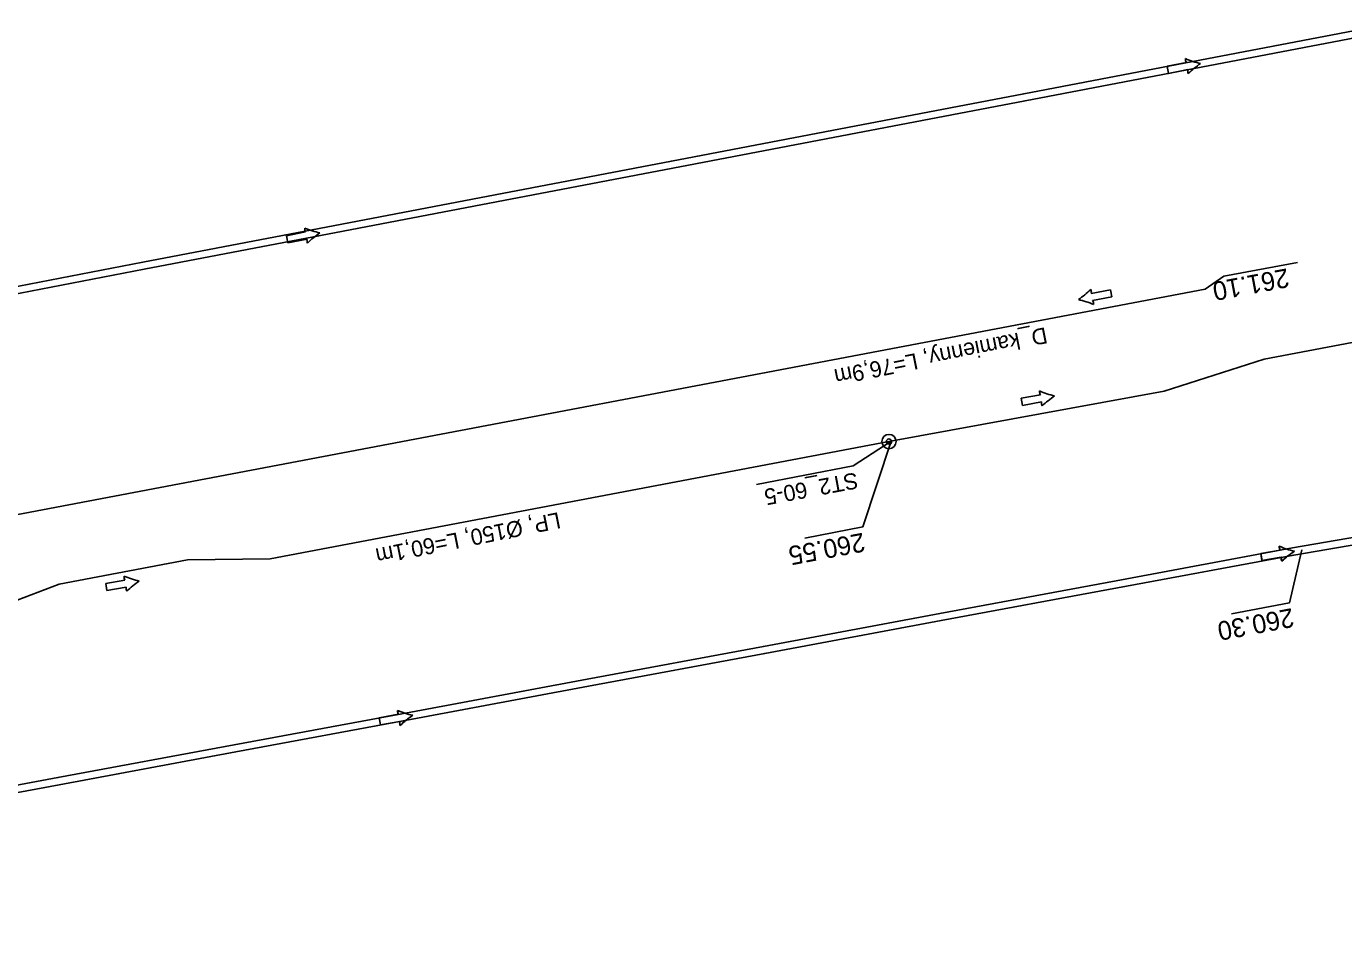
# Model space of a CAD drawing. Extents: x -1 to 65640748, y -22 to 5530284.
# Drawn here: x 6558708.2 to 6558781.6, y 5528891 to 5528942.3 of the extents above; entities that cross this region are included whole.
import ezdxf

# ---------------------------------------------------------------- set-up
doc = ezdxf.new("R2010")
doc.units = 0
for name, color, linetype in [('TOR_PS_ODW-drenaze', 7, 'Continuous'), ('TOR_PS_ODW-drenokolektory', 7, 'Continuous'), ('TOR_PS_ODW-studnie PEHD', 7, 'Continuous'), ('TOR_PS_OPIS_O-opisy rurociagow', 7, 'Continuous'), ('TOR_PS_OPIS_O-opisy studni', 7, 'Continuous'), ('TOR_PS_OPIS_T-INFO', 7, 'Continuous'), ('TOR_PS_T-rowy otwarte umocnione', 7, 'Continuous')]:
    doc.layers.add(name, color=color, linetype=linetype)

msp = doc.modelspace()

# ---------------------------------------------------------------- linework, layer by layer
at = {"layer": 'TOR_PS_ODW-drenaze'}
msp.add_line((6558773.925, 5528927.61), (6558698.366, 5528913.287), dxfattribs=at)
at = {"layer": 'TOR_PS_ODW-drenokolektory'}
for points in [[(6558810.39, 5528929.053), (6558807.044, 5528928.439), (6558801.771, 5528928.372), (6558793.907, 5528926.881), (6558787.408, 5528925.65), (6558777.206, 5528923.716), (6558771.626, 5528921.937), (6558756.292, 5528919.127)], [(6558756.292, 5528919.127), (6558721.8, 5528912.589), (6558717.193, 5528912.53), (6558710.034, 5528911.173), (6558705.725, 5528909.542), (6558705.725, 5528909.542), (6558697.342, 5528907.953)]]:
    msp.add_lwpolyline(points, dxfattribs=at)
at = {"layer": 'TOR_PS_ODW-studnie PEHD'}
for radius in [0.4, 0.145]:
    msp.add_circle((6558756.292, 5528919.127), radius, dxfattribs=at)
at = {"layer": 'TOR_PS_OPIS_O-opisy rurociagow'}
for p, q in [((6558772.874, 5528940.248), (6558771.801, 5528940.041)), ((6558772.874, 5528940.248), (6558771.801, 5528940.041)), ((6558772.874, 5528940.248), (6558771.801, 5528940.041)), ((6558772.874, 5528940.248), (6558771.801, 5528940.041)), ((6558771.801, 5528940.041), (6558771.876, 5528939.648)), ((6558771.801, 5528940.041), (6558771.876, 5528939.648)), ((6558771.801, 5528940.041), (6558771.876, 5528939.648)), ((6558771.801, 5528940.041), (6558771.876, 5528939.648)), ((6558771.876, 5528939.648), (6558772.949, 5528939.855)), ((6558772.949, 5528939.855), (6558771.876, 5528939.648)), ((6558771.876, 5528939.648), (6558772.949, 5528939.855)), ((6558772.949, 5528939.855), (6558771.876, 5528939.648)), ((6558723.773, 5528930.805), (6558722.7, 5528930.599)), ((6558723.773, 5528930.805), (6558722.7, 5528930.599)), ((6558723.773, 5528930.805), (6558722.7, 5528930.599)), ((6558723.773, 5528930.805), (6558722.7, 5528930.599)), ((6558722.7, 5528930.599), (6558722.776, 5528930.206)), ((6558722.7, 5528930.599), (6558722.776, 5528930.206)), ((6558722.7, 5528930.599), (6558722.776, 5528930.206)), ((6558722.7, 5528930.599), (6558722.776, 5528930.206)), ((6558722.776, 5528930.206), (6558723.849, 5528930.413)), ((6558723.849, 5528930.413), (6558722.776, 5528930.206)), ((6558722.776, 5528930.206), (6558723.849, 5528930.413)), ((6558723.849, 5528930.413), (6558722.776, 5528930.206)), ((6558768.647, 5528927.581), (6558767.573, 5528927.378)), ((6558767.573, 5528927.378), (6558768.647, 5528927.581)), ((6558768.721, 5528927.188), (6558768.647, 5528927.581)), ((6558768.721, 5528927.188), (6558768.647, 5528927.581)), ((6558767.648, 5528926.985), (6558768.721, 5528927.188)), ((6558767.648, 5528926.985), (6558768.721, 5528927.188)), ((6558764.734, 5528921.726), (6558763.659, 5528921.535)), ((6558764.734, 5528921.726), (6558763.659, 5528921.535)), ((6558763.659, 5528921.535), (6558763.729, 5528921.141)), ((6558763.659, 5528921.535), (6558763.729, 5528921.141)), ((6558763.729, 5528921.141), (6558764.805, 5528921.332)), ((6558764.805, 5528921.332), (6558763.729, 5528921.141)), ((6558778.099, 5528913.074), (6558777.022, 5528912.892)), ((6558778.099, 5528913.074), (6558777.022, 5528912.892)), ((6558778.099, 5528913.074), (6558777.022, 5528912.892)), ((6558778.099, 5528913.074), (6558777.022, 5528912.892)), ((6558777.022, 5528912.892), (6558777.089, 5528912.497)), ((6558777.022, 5528912.892), (6558777.089, 5528912.497)), ((6558777.022, 5528912.892), (6558777.089, 5528912.497)), ((6558777.022, 5528912.892), (6558777.089, 5528912.497)), ((6558778.107, 5528913.076), (6558777.03, 5528912.893)), ((6558778.107, 5528913.076), (6558777.03, 5528912.893)), ((6558777.03, 5528912.893), (6558777.097, 5528912.499)), ((6558777.03, 5528912.893), (6558777.097, 5528912.499)), ((6558777.089, 5528912.497), (6558778.166, 5528912.68)), ((6558778.166, 5528912.68), (6558777.089, 5528912.497)), ((6558777.089, 5528912.497), (6558778.166, 5528912.68)), ((6558778.166, 5528912.68), (6558777.089, 5528912.497)), ((6558777.097, 5528912.499), (6558778.174, 5528912.681)), ((6558778.174, 5528912.681), (6558777.097, 5528912.499)), ((6558713.7, 5528911.407), (6558712.625, 5528911.215)), ((6558713.7, 5528911.407), (6558712.625, 5528911.215)), ((6558712.625, 5528911.215), (6558712.695, 5528910.821)), ((6558712.625, 5528911.215), (6558712.695, 5528910.821)), ((6558712.695, 5528910.821), (6558713.77, 5528911.013)), ((6558713.77, 5528911.013), (6558712.695, 5528910.821)), ((6558728.944, 5528903.922), (6558727.87, 5528903.722)), ((6558728.944, 5528903.922), (6558727.87, 5528903.722)), ((6558728.944, 5528903.922), (6558727.87, 5528903.722)), ((6558728.944, 5528903.922), (6558727.87, 5528903.722)), ((6558728.946, 5528903.922), (6558727.871, 5528903.722)), ((6558728.946, 5528903.922), (6558727.871, 5528903.722)), ((6558727.87, 5528903.722), (6558727.943, 5528903.329)), ((6558727.87, 5528903.722), (6558727.943, 5528903.329)), ((6558727.87, 5528903.722), (6558727.943, 5528903.329)), ((6558727.87, 5528903.722), (6558727.943, 5528903.329)), ((6558727.871, 5528903.722), (6558727.945, 5528903.329)), ((6558727.871, 5528903.722), (6558727.945, 5528903.329)), ((6558727.943, 5528903.329), (6558729.017, 5528903.528)), ((6558729.017, 5528903.528), (6558727.943, 5528903.329)), ((6558727.943, 5528903.329), (6558729.017, 5528903.528)), ((6558729.017, 5528903.528), (6558727.943, 5528903.329)), ((6558727.945, 5528903.329), (6558729.019, 5528903.529)), ((6558729.019, 5528903.529), (6558727.945, 5528903.329))]:
    msp.add_line(p, q, dxfattribs=at)
for points in [[(6558772.821, 5528940.466), (6558772.821, 5528940.466)], [(6558772.821, 5528940.466), (6558772.821, 5528940.466)], [(6558772.981, 5528939.632), (6558772.981, 5528939.632)], [(6558772.981, 5528939.632), (6558772.981, 5528939.632)], [(6558723.721, 5528931.024), (6558723.721, 5528931.024)], [(6558723.721, 5528931.024), (6558723.721, 5528931.024)], [(6558723.881, 5528930.19), (6558723.881, 5528930.19)], [(6558723.881, 5528930.19), (6558723.881, 5528930.19)], [(6558767.541, 5528927.601), (6558767.541, 5528927.601)], [(6558767.7, 5528926.766), (6558767.7, 5528926.766)], [(6558764.685, 5528921.946), (6558764.685, 5528921.946)], [(6558764.834, 5528921.109), (6558764.834, 5528921.109)], [(6558778.051, 5528913.294), (6558778.051, 5528913.294)], [(6558778.051, 5528913.294), (6558778.051, 5528913.294)], [(6558778.059, 5528913.296), (6558778.059, 5528913.296)], [(6558778.193, 5528912.457), (6558778.193, 5528912.457)], [(6558778.193, 5528912.457), (6558778.193, 5528912.457)], [(6558778.202, 5528912.458), (6558778.202, 5528912.458)], [(6558713.651, 5528911.626), (6558713.651, 5528911.626)], [(6558713.8, 5528910.79), (6558713.8, 5528910.79)], [(6558728.893, 5528904.141), (6558728.893, 5528904.141)], [(6558728.893, 5528904.141), (6558728.893, 5528904.141)], [(6558728.894, 5528904.141), (6558728.894, 5528904.141)], [(6558729.048, 5528903.305), (6558729.048, 5528903.305)], [(6558729.048, 5528903.305), (6558729.048, 5528903.305)], [(6558729.05, 5528903.306), (6558729.05, 5528903.306)]]:
    msp.add_lwpolyline(points, dxfattribs=at)
for centre, radius, start, end in [((6558774.728, 5528944.999), 4.918, 247.17871, 257.56053), ((6558773.279, 5528940.461), 0.458, 179.29327, 207.75451), ((6558774.728, 5528944.999), 4.918, 247.17871, 257.56053), ((6558773.279, 5528940.461), 0.458, 179.29327, 207.75451), ((6558774.728, 5528944.999), 4.918, 247.17871, 257.56053), ((6558773.279, 5528940.461), 0.458, 179.29327, 207.75451), ((6558774.728, 5528944.999), 4.918, 247.17871, 257.56053), ((6558773.279, 5528940.461), 0.458, 179.29327, 207.75451), ((6558773.405, 5528939.807), 0.458, 174.02262, 202.48386), ((6558773.405, 5528939.807), 0.458, 174.02262, 202.48386), ((6558773.405, 5528939.807), 0.458, 174.02262, 202.48386), ((6558773.405, 5528939.807), 0.458, 174.02262, 202.48386), ((6558776.434, 5528936.13), 4.918, 124.21659, 134.59842), ((6558776.434, 5528936.13), 4.918, 124.21659, 134.59842), ((6558776.434, 5528936.13), 4.918, 124.21659, 134.59842), ((6558776.434, 5528936.13), 4.918, 124.21659, 134.59842), ((6558725.628, 5528935.557), 4.918, 247.17871, 257.56053), ((6558724.178, 5528931.019), 0.458, 179.29327, 207.75451), ((6558725.628, 5528935.557), 4.918, 247.17871, 257.56053), ((6558724.178, 5528931.019), 0.458, 179.29327, 207.75451), ((6558725.628, 5528935.557), 4.918, 247.17871, 257.56053), ((6558724.178, 5528931.019), 0.458, 179.29327, 207.75451), ((6558725.628, 5528935.557), 4.918, 247.17871, 257.56053), ((6558724.178, 5528931.019), 0.458, 179.29327, 207.75451), ((6558724.304, 5528930.365), 0.458, 174.02262, 202.48386), ((6558724.304, 5528930.365), 0.458, 174.02262, 202.48386), ((6558724.304, 5528930.365), 0.458, 174.02262, 202.48386), ((6558724.304, 5528930.365), 0.458, 174.02262, 202.48386), ((6558727.334, 5528926.688), 4.918, 124.21659, 134.59842), ((6558727.334, 5528926.688), 4.918, 124.21659, 134.59842), ((6558727.334, 5528926.688), 4.918, 124.21659, 134.59842), ((6558727.334, 5528926.688), 4.918, 124.21659, 134.59842), ((6558764.098, 5528931.112), 4.918, 304.06127, 314.4431), ((6558764.098, 5528931.112), 4.918, 304.06127, 314.4431), ((6558767.118, 5528927.427), 0.458, 353.86729, 22.32853), ((6558767.118, 5528927.427), 0.458, 353.86729, 22.32853), ((6558765.78, 5528922.238), 4.918, 67.02338, 77.40521), ((6558765.78, 5528922.238), 4.918, 67.02338, 77.40521), ((6558767.242, 5528926.773), 0.458, 359.13794, 27.59919), ((6558767.242, 5528926.773), 0.458, 359.13794, 27.59919), ((6558766.655, 5528926.452), 4.918, 246.38098, 256.76281), ((6558765.142, 5528921.934), 0.458, 178.49555, 206.95679), ((6558766.655, 5528926.452), 4.918, 246.38098, 256.76281), ((6558765.142, 5528921.934), 0.458, 178.49555, 206.95679), ((6558768.238, 5528917.56), 4.918, 123.41887, 133.8007), ((6558768.238, 5528917.56), 4.918, 123.41887, 133.8007), ((6558765.259, 5528921.278), 0.458, 173.22489, 201.68613), ((6558765.259, 5528921.278), 0.458, 173.22489, 201.68613), ((6558780.057, 5528917.784), 4.918, 245.92481, 256.30664), ((6558778.509, 5528913.279), 0.458, 178.03937, 206.50061), ((6558780.057, 5528917.784), 4.918, 245.92481, 256.30664), ((6558778.509, 5528913.279), 0.458, 178.03937, 206.50061), ((6558780.057, 5528917.784), 4.918, 245.92481, 256.30664), ((6558778.509, 5528913.279), 0.458, 178.03937, 206.50061), ((6558780.057, 5528917.784), 4.918, 245.92481, 256.30664), ((6558778.509, 5528913.279), 0.458, 178.03937, 206.50061), ((6558780.065, 5528917.786), 4.918, 245.92481, 256.30664), ((6558778.517, 5528913.28), 0.458, 178.03937, 206.50061), ((6558780.065, 5528917.786), 4.918, 245.92481, 256.30664), ((6558778.517, 5528913.28), 0.458, 178.03937, 206.50061), ((6558778.62, 5528912.622), 0.458, 172.76872, 201.22996), ((6558778.62, 5528912.622), 0.458, 172.76872, 201.22996), ((6558778.62, 5528912.622), 0.458, 172.76872, 201.22996), ((6558778.62, 5528912.622), 0.458, 172.76872, 201.22996), ((6558778.628, 5528912.624), 0.458, 172.76872, 201.22996), ((6558778.628, 5528912.624), 0.458, 172.76872, 201.22996), ((6558781.569, 5528908.88), 4.918, 122.9627, 133.34453), ((6558781.569, 5528908.88), 4.918, 122.9627, 133.34453), ((6558781.569, 5528908.88), 4.918, 122.9627, 133.34453), ((6558781.569, 5528908.88), 4.918, 122.9627, 133.34453), ((6558781.577, 5528908.882), 4.918, 122.9627, 133.34453), ((6558781.577, 5528908.882), 4.918, 122.9627, 133.34453), ((6558715.621, 5528916.132), 4.918, 246.38098, 256.76281), ((6558714.108, 5528911.614), 0.458, 178.49555, 206.95679), ((6558715.621, 5528916.132), 4.918, 246.38098, 256.76281), ((6558714.108, 5528911.614), 0.458, 178.49555, 206.95679), ((6558717.204, 5528907.24), 4.918, 123.41887, 133.8007), ((6558717.204, 5528907.24), 4.918, 123.41887, 133.8007), ((6558714.225, 5528910.959), 0.458, 173.22489, 201.68613), ((6558714.225, 5528910.959), 0.458, 173.22489, 201.68613), ((6558730.828, 5528908.662), 4.918, 246.82357, 257.2054), ((6558729.35, 5528904.132), 0.458, 178.93813, 207.39937), ((6558730.828, 5528908.662), 4.918, 246.82357, 257.2054), ((6558729.35, 5528904.132), 0.458, 178.93813, 207.39937), ((6558730.828, 5528908.662), 4.918, 246.82357, 257.2054), ((6558729.35, 5528904.132), 0.458, 178.93813, 207.39937), ((6558730.828, 5528908.662), 4.918, 246.82357, 257.2054), ((6558729.35, 5528904.132), 0.458, 178.93813, 207.39937), ((6558730.83, 5528908.662), 4.918, 246.82252, 257.20435), ((6558729.352, 5528904.133), 0.458, 178.93708, 207.39833), ((6558730.83, 5528908.662), 4.918, 246.82252, 257.20435), ((6558729.352, 5528904.133), 0.458, 178.93708, 207.39833), ((6558732.479, 5528899.782), 4.918, 123.86146, 134.24328), ((6558732.479, 5528899.782), 4.918, 123.86146, 134.24328), ((6558732.479, 5528899.782), 4.918, 123.86146, 134.24328), ((6558732.479, 5528899.782), 4.918, 123.86146, 134.24328), ((6558732.481, 5528899.783), 4.918, 123.86041, 134.24224), ((6558732.481, 5528899.783), 4.918, 123.86041, 134.24224), ((6558729.472, 5528903.478), 0.458, 173.66748, 202.12872), ((6558729.472, 5528903.478), 0.458, 173.66748, 202.12872), ((6558729.472, 5528903.478), 0.458, 173.66748, 202.12872), ((6558729.472, 5528903.478), 0.458, 173.66748, 202.12872), ((6558729.474, 5528903.478), 0.458, 173.66643, 202.12767), ((6558729.474, 5528903.478), 0.458, 173.66643, 202.12767)]:
    msp.add_arc(centre, radius, start, end, dxfattribs=at)
at = {"layer": 'TOR_PS_OPIS_T-INFO'}
for points in [[(6558773.925, 5528927.61), (6558774.968, 5528928.346), (6558779.068, 5528929.109)], [(6558756.413, 5528919.151), (6558754.297, 5528917.766), (6558748.899, 5528916.725)], [(6558756.413, 5528919.151), (6558754.83, 5528914.368), (6558751.597, 5528913.744)], [(6558779.302, 5528913.095), (6558778.626, 5528910.144), (6558775.392, 5528909.52)]]:
    msp.add_lwpolyline(points, dxfattribs=at)
at = {"layer": 'TOR_PS_T-rowy otwarte umocnione'}
for points in [[(6558783.453, 5528942.267), (6558773.631, 5528940.388), (6558763.809, 5528938.51), (6558753.987, 5528936.631), (6558744.165, 5528934.753), (6558734.343, 5528932.874), (6558724.521, 5528930.995), (6558714.699, 5528929.117), (6558704.878, 5528927.235), (6558695.066, 5528925.303), (6558685.254, 5528923.371), (6558675.442, 5528921.439), (6558665.63, 5528919.507), (6558656.34, 5528917.678), (6558656.415, 5528917.285)], [(6558783.528, 5528941.874), (6558773.706, 5528939.995), (6558763.884, 5528938.117), (6558754.062, 5528936.238), (6558744.24, 5528934.36), (6558734.418, 5528932.481), (6558724.596, 5528930.602), (6558714.774, 5528928.724), (6558704.952, 5528926.842), (6558695.14, 5528924.91), (6558685.329, 5528922.978), (6558675.517, 5528921.046), (6558665.705, 5528919.114), (6558656.415, 5528917.285)], [(6558788.643, 5528914.885), (6558778.786, 5528913.192), (6558768.955, 5528911.363), (6558759.123, 5528909.535), (6558749.292, 5528907.707), (6558739.46, 5528905.878), (6558729.629, 5528904.05), (6558719.797, 5528902.222), (6558709.966, 5528900.393), (6558700.134, 5528898.565), (6558690.303, 5528896.737), (6558680.47, 5528894.913), (6558670.613, 5528893.224), (6558661.279, 5528891.624), (6558660.755, 5528891.535), (6558659.769, 5528891.366), (6558659.843, 5528890.973)], [(6558788.718, 5528914.492), (6558778.861, 5528912.799), (6558769.029, 5528910.97), (6558759.198, 5528909.142), (6558749.366, 5528907.314), (6558739.535, 5528905.485), (6558729.703, 5528903.657), (6558719.872, 5528901.829), (6558710.04, 5528900), (6558700.209, 5528898.172), (6558690.377, 5528896.344), (6558680.545, 5528894.52), (6558670.687, 5528892.831), (6558661.353, 5528891.231), (6558660.829, 5528891.142), (6558659.843, 5528890.973)]]:
    msp.add_lwpolyline(points, dxfattribs=at)

# ---------------------------------------------------------------- texts
at = {"layer": 'TOR_PS_OPIS_O-opisy rurociagow'}
for s, p in [('D_kamienny, L=76,9m', (6558765.016, 5528925.505)), ('LP, Ø150, L=60,1m', (6558737.877, 5528915.198))]:
    msp.add_text(s, height=0.9, rotation=191.29864, dxfattribs=at).set_placement(p)
at = {"layer": 'TOR_PS_OPIS_O-opisy studni'}
msp.add_text('ST2_60-5', height=0.9, rotation=190.53513, dxfattribs=at).set_placement((6558754.479, 5528917.417))
at = {"layer": 'TOR_PS_OPIS_T-INFO'}
for s, p in [('261.10', (6558778.488, 5528928.786)), ('260.55', (6558754.843, 5528914.049)), ('260.30', (6558778.757, 5528909.848))]:
    msp.add_text(s, height=1.05, rotation=190.71587, dxfattribs=at).set_placement(p)

doc.saveas('drawing.dxf')
